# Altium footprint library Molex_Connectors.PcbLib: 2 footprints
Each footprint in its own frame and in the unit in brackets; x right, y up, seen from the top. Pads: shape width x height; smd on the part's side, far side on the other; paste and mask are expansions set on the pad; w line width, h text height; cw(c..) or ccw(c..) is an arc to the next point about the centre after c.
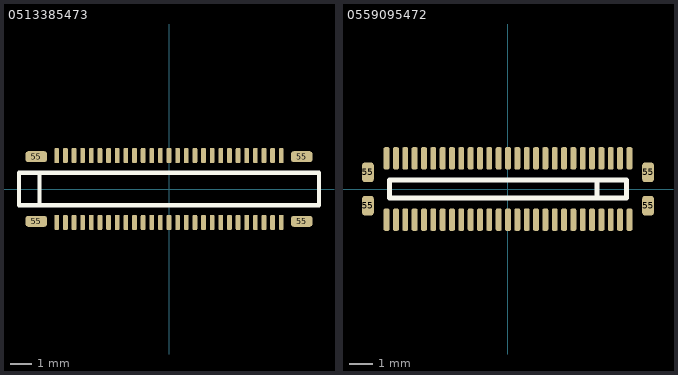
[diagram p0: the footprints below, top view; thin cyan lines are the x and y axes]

## 0513385473 [mm] "Molex 052338 Series Connector - 54 pin"
pads (58):
  rrect50% 0.22x0.7 smd: 1(-5.2,-1.55) 2(-4.8,-1.55) 3(-4.4,-1.55) 4(-4,-1.55) 5(-3.6,-1.55) 6(-3.2,-1.55) 7(-2.8,-1.55) 8(-2.4,-1.55) 9(-2,-1.55) 10(-1.6,-1.55) 11(-1.2,-1.55) 12(-0.8,-1.55) 13(-0.4,-1.55) 14(0,-1.55) 15(0.4,-1.55) 16(0.8,-1.55) 17(1.2,-1.55) 18(1.6,-1.55) 19(2,-1.55) 20(2.4,-1.55) 21(2.8,-1.55) 22(3.2,-1.55) 23(3.6,-1.55) 24(4,-1.55) 25(4.4,-1.55) 26(4.8,-1.55) 27(5.2,-1.55) 28(5.2,1.55) 29(4.8,1.55) 30(4.4,1.55) 31(4,1.55) 32(3.6,1.55) 33(3.2,1.55) 34(2.8,1.55) 35(2.4,1.55) 36(2,1.55) 37(1.6,1.55) 38(1.2,1.55) 39(0.8,1.55) 40(0.4,1.55) 41(0,1.55) 42(-0.4,1.55) 43(-0.8,1.55) 44(-1.2,1.55) 45(-1.6,1.55) 46(-2,1.55) 47(-2.4,1.55) 48(-2.8,1.55) 49(-3.2,1.55) 50(-3.6,1.55) 51(-4,1.55) 52(-4.4,1.55) 53(-4.8,1.55) 54(-5.2,1.55)
  rrect50% 1x0.5 smd: 55(-6.15,-1.5) 55(-6.15,1.5) 55(6.15,-1.5) 55(6.15,1.5)
Top Overlay:
  lines w0.203: -6,-0.75 -6,0.75 ; -6.95,-0.75 -6.95,0.75 6.95,0.75 6.95,-0.75 -6.95,-0.75
3D body: height 1.37, standoff -0.03, extent -6.95,-1.705 6.95,1.705

## 0559095472 [mm] "Molex 055909 Series Connector - 54 pin"
pads (58):
  rrect50% 0.25x0.95 smd: 1(-5.2,-1.315) 2(-4.8,-1.315) 3(-4.4,-1.315) 4(-4,-1.315) 5(-3.6,-1.315) 6(-3.2,-1.315) 7(-2.8,-1.315) 8(-2.4,-1.315) 9(-2,-1.315) 10(-1.6,-1.315) 11(-1.2,-1.315) 12(-0.8,-1.315) 13(-0.4,-1.315) 14(0,-1.315) 15(0.4,-1.315) 16(0.8,-1.315) 17(1.2,-1.315) 18(1.6,-1.315) 19(2,-1.315) 20(2.4,-1.315) 21(2.8,-1.315) 22(3.2,-1.315) 23(3.6,-1.315) 24(4,-1.315) 25(4.4,-1.315) 26(4.8,-1.315) 27(5.2,-1.315) 28(5.2,1.315) 29(4.8,1.315) 30(4.4,1.315) 31(4,1.315) 32(3.6,1.315) 33(3.2,1.315) 34(2.8,1.315) 35(2.4,1.315) 36(2,1.315) 37(1.6,1.315) 38(1.2,1.315) 39(0.8,1.315) 40(0.4,1.315) 41(0,1.315) 42(-0.4,1.315) 43(-0.8,1.315) 44(-1.2,1.315) 45(-1.6,1.315) 46(-2,1.315) 47(-2.4,1.315) 48(-2.8,1.315) 49(-3.2,1.315) 50(-3.6,1.315) 51(-4,1.315) 52(-4.4,1.315) 53(-4.8,1.315) 54(-5.2,1.315)
  rrect50% 0.5x0.85 smd: 55(-6,-0.715) 55(-6,0.715) 55(6,-0.715) 55(6,0.715)
Top Overlay:
  lines w0.203: 3.81,-0.381 3.81,0.381 ; -5.08,-0.381 5.08,-0.381 5.08,0.381 -5.08,0.381 -5.08,-0.381
3D body: height 1.17, standoff -0.03, extent -6.4,-1.565 6.4,1.565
